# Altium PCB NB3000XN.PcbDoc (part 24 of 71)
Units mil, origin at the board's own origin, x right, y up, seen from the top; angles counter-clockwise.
Board outline 9527.56 x 6929.77 mil, 6 copper layers (Top Layer, GND+SHIELD, MidLayer1, MidLayer2, P2 - 3V3+5V0, Bottom Layer), stack 62.375 mil thick; 832 components, 1027 nets, 4655 pads, 4981 vias.
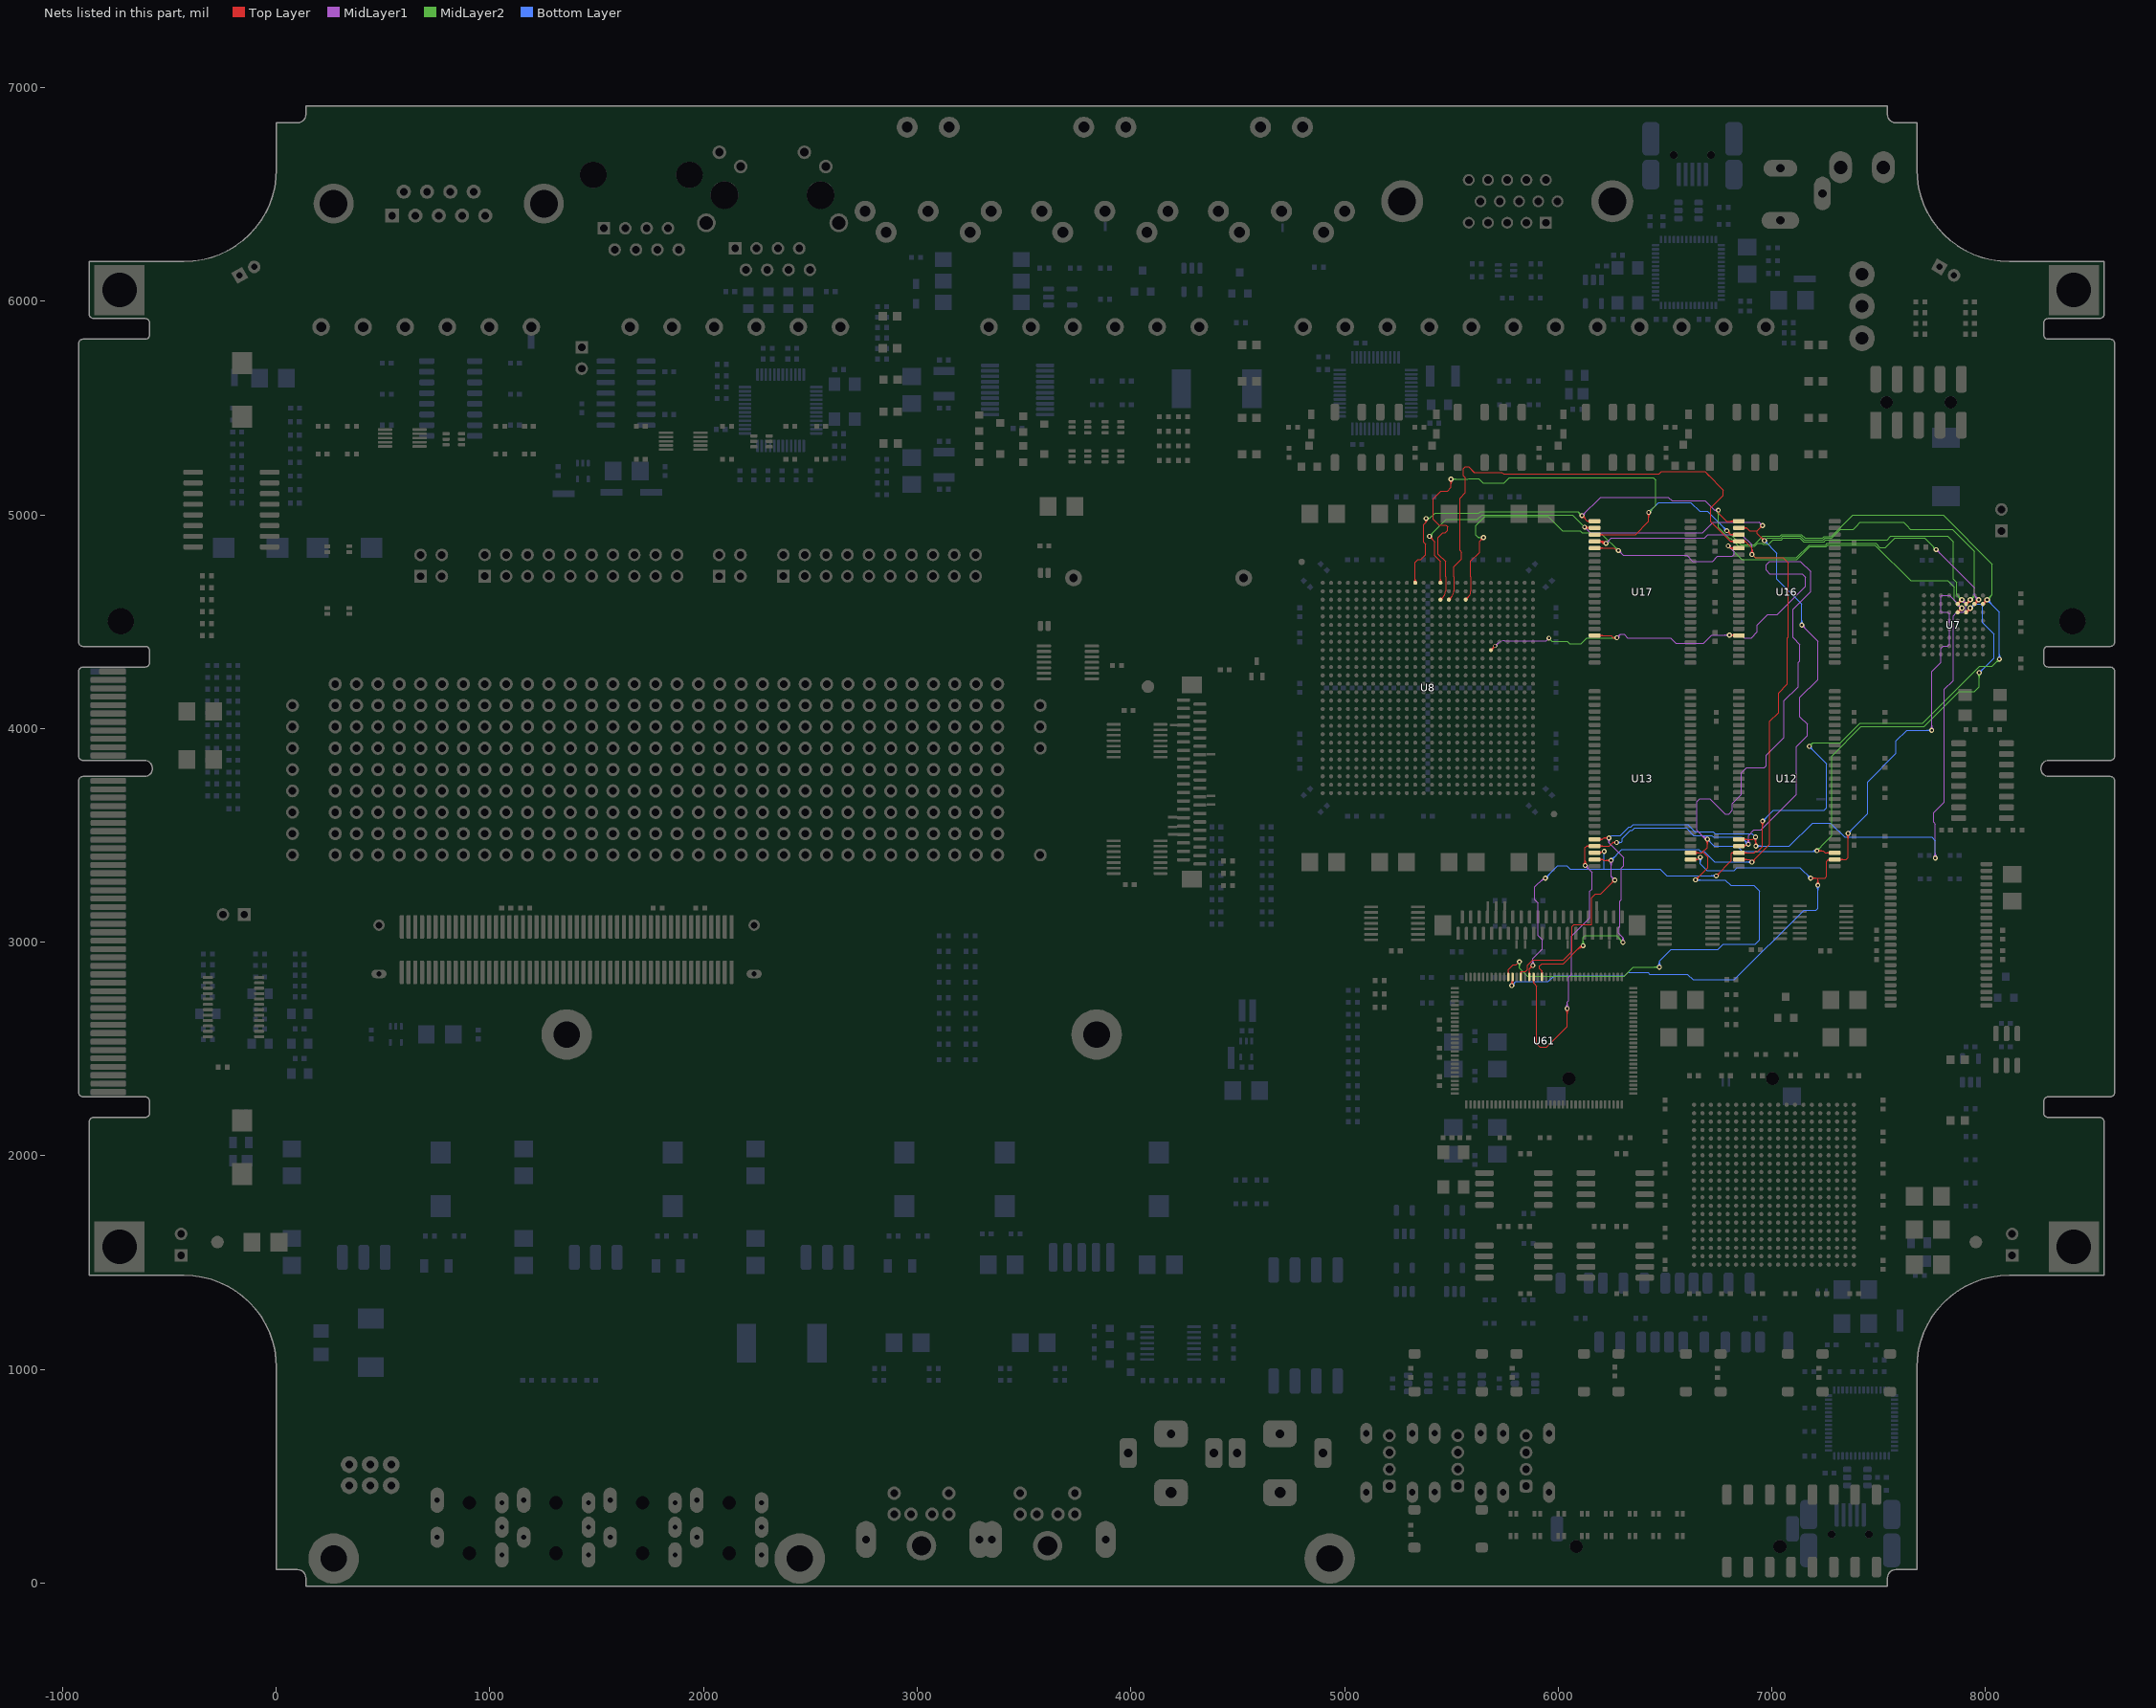
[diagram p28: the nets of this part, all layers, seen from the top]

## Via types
v1: diameter 23, hole 11.81, Top Layer to Bottom Layer, 3672 vias
v2: diameter 26, hole 11.81, Top Layer to Bottom Layer, 461 vias
v3: diameter 19, hole 11.81, Top Layer to Bottom Layer, tented both sides, 396 vias
v4: diameter 23.62, hole 11.81, Top Layer to Bottom Layer, 288 vias
v5: diameter 20, hole 11.81, Top Layer to Bottom Layer, 91 vias
v6: diameter 23, hole 11.81, Top Layer to Bottom Layer, tented both sides, 50 vias
v7: diameter 31, hole 11.81, Top Layer to Bottom Layer, 15 vias
v8: diameter 27.56, hole 11.81, Top Layer to Bottom Layer, tented both sides, 4 vias
v9: diameter 29, hole 11.81, Top Layer to Bottom Layer, 3 vias
v10: diameter 21, hole 11.81, Top Layer to Bottom Layer, 1 vias

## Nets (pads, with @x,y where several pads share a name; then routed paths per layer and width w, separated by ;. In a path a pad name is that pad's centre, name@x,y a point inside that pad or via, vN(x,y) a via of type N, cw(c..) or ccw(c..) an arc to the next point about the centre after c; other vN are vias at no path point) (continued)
DB_MEM.BUS_A2: U7.D2 U8.A12 U12.23 U13.23 U16.1 U17.1 U61.84 | length 9169.9
  Top Layer w4: U8.A12@5325.64,4687.43 ccw(c5312.84,4700.23) 5330.94,4700.23 ccw(c5349.05,4700.23) U8.A12@5336.25,4687.43 ; U8.A12@5325.75,4687.32 ccw(c5313.22,4699.85) 5330.94,4699.85 ccw(c5348.67,4699.85) U8.A12@5336.14,4687.32 ; U8.A12@5330.94,4682.13 5330.94,4710 5330.94,4720 5330.94,4724.74 5330.95,4728.71 5330.95,4778.21 5343.74,4791 5357.13,4791 5379.5,4813.37 5379.5,4863.42 5371.19,4871.73 5371.19,4955.04 5381.86,4965.71 ; v1@5376.62,4975.45 cw(c5370.18,4965.71) 5381.86,4965.71 ; v1(5381.86,4983.37) 5381.86,4965.71 ; v1@5387.1,4975.45 ccw(c5393.53,4965.71) 5381.86,4965.71 ; U61.84@5921.5,2853.36 ccw(c5914.67,2860.19) 5924.33,2860.19 ccw(c5933.99,2860.19) U61.84@5927.16,2853.36 ; U61.84@5924.33,2837.34 5924.33,2864.53 5913.36,2875.5 5913.36,2889.88 5916.78,2893.3 5923.52,2900.04 6024.52,2900.04 6107.86,2983.37 v1(6116.86,2983.37) ; 6085.28,2960.79 cw(c6116.86,2929.21) v1@6116.86,2973.87 ; 6092.1,2967.62 cw(c6116.86,2942.87) v1@6116.86,2977.87 ; 6098.93,2974.45 cw(c6116.86,2956.53) v1@6116.86,2981.87 ; v1@6111.52,4987.21 cw(c6111.52,4964.27) 6127.74,4980.49 cw(c6143.96,4996.71) v1@6121.02,4996.71 ; v1@6111.52,4991.21 cw(c6111.52,4977.93) 6120.91,4987.32 cw(c6130.3,4996.71) v1@6117.02,4996.71 ; v1(6111.52,4996.71) 6137.53,4970.71 ; U17.1@6146.51,4966.07 ccw(c6137.53,4959.68) 6137.53,4970.71 ; U17.1@6146.51,4975.34 cw(c6137.53,4981.73) 6137.53,4970.71 ; U13.23@6170.59,3481.54 6206.35,3481.53 ; U17.1@6170.59,4970.71 6137.53,4970.71 ; U13.23@6194.04,3476.13 cw(c6206.35,3464.83) 6206.35,3481.53 ; U13.23@6194.04,3486.94 ccw(c6206.35,3498.23) 6206.35,3481.53 ; v1@6231.14,3481.32 ccw(c6214.92,3465.11) 6214.92,3488.04 ccw(c6214.92,3510.98) v1@6231.14,3494.76 ; v1@6233.97,3484.15 ccw(c6224.58,3474.76) 6224.58,3488.04 ccw(c6224.58,3501.32) v1@6233.97,3491.93 ; v1(6237.86,3488.04) 6212.86,3488.04 6206.35,3481.53 ; v1(6749.52,5022.37) 6749.52,5008.37 6787.19,4970.71 U16.1@6845.59,4970.71 ; U16.1@6822.37,4965.05 ccw(c6808.72,4951.4) 6808.72,4970.71 ccw(c6808.72,4990.02) U16.1@6822.37,4976.37 ; U12.23@6845.59,3481.54 6912.35,3481.53 v1(6923.52,3492.71) 6923.52,3472 ; U12.23@6868.81,3475.88 cw(c6882.46,3462.22) 6882.46,3481.53 cw(c6882.46,3500.85) U12.23@6868.81,3487.19 ; v1@6917.33,3485.51 cw(c6905.71,3472) 6923.52,3472 ; v1@6919.53,3457.41 ccw(c6909.31,3470) 6925.52,3470 ccw(c6941.74,3470) v1@6931.51,3457.41 ; v1@6919.94,3488.54 cw(c6913.21,3480.72) 6923.52,3480.72 cw(c6933.84,3480.72) v1@6927.11,3488.54 ; v1@6922.06,3454.31 ccw(c6916.14,3461.6) 6925.52,3461.6 ccw(c6934.91,3461.6) v1@6928.99,3454.31 ; v1(6925.52,3450.04) 6925.52,3470 6923.52,3472 ; v1@6929.72,3485.51 ccw(c6941.34,3472) 6923.52,3472
  Top Layer w8: U7.D2@7869.69,4583.43 v2(7889.37,4603.11) ; U7.D2@7869.69,4589.43 ccw(c7869.69,4603.91) 7879.93,4593.67 ccw(c7890.17,4583.43) U7.D2@7875.69,4583.43 ; v2@7880.37,4603.11 cw(c7858.64,4603.11) 7874.01,4587.75 cw(c7889.37,4572.38) v2@7889.37,4594.11
  MidLayer1 w4: v1(6111.52,4996.71) 6198.19,5083.37 6515.19,5083.37 6531.86,5066.71 6687.21,5066.71 6731.54,5022.37 ; v1@6111.52,5002.21 ccw(c6111.52,5015.49) 6120.91,5006.1 ccw(c6130.3,4996.71) v1@6117.02,4996.71 ; v1@6111.52,5006.21 ccw(c6111.52,5029.14) 6127.74,5012.93 ccw(c6143.96,4996.71) v1@6121.02,4996.71 ; v1@6231.14,3481.32 cw(c6214.92,3465.11) 6237.86,3465.11 cw(c6260.79,3465.11) v1@6244.57,3481.32 ; v1@6233.97,3484.15 cw(c6224.58,3474.76) 6237.86,3474.76 cw(c6251.14,3474.76) v1@6241.75,3484.15 ; v1(6237.86,3488.04) 6237.86,3464.69 6307.52,3395.02 6307.52,3358.73 6295.52,3346.73 6295.52,3198.04 6289.19,3191.71 6289.19,3074.04 6281.86,3066.71 6281.86,3041.71 6303.52,3020.04 ; v1@6297.25,3006.18 ccw(c6285.07,3020.04) 6303.52,3020.04 ; v1@6299.89,3003.17 ccw(c6292.84,3011.2) 6303.52,3011.2 ccw(c6314.21,3011.2) v1@6307.16,3003.17 ; v1(6303.52,2999.04) 6303.52,3020.04 ; v1@6309.8,3006.18 cw(c6321.98,3020.04) 6303.52,3020.04 ; v1@6741.68,5017.02 ccw(c6731.54,5010.11) 6731.54,5022.37 ; v1@6741.68,5027.73 cw(c6731.54,5034.64) 6731.54,5022.37 ; v1(6749.52,5022.37) 6731.54,5022.37 ; v1@7758.47,3400.43 ccw(c7742.26,3416.64) 7765.19,3416.64 ccw(c7788.13,3416.64) v1@7771.91,3400.43 ; v1@7761.3,3397.6 ccw(c7751.91,3406.99) 7765.19,3406.99 ccw(c7778.47,3406.99) v1@7769.08,3397.6 ; v1(7765.19,3393.71) 7765.19,3553.69 7756.86,3562.02 7756.86,3606.02 7807.19,3656.35 7807.19,4184.02 7848.52,4225.36 7848.52,4528.04 7865.19,4544.71 7897.52,4544.71 7908.52,4555.71 7908.52,4583.96 v2(7889.37,4603.11) ; v2@7889.37,4592.11 cw(c7889.37,4565.55) 7908.15,4584.33 cw(c7926.93,4603.11) v2@7900.37,4603.11 ; v2@7889.37,4596.11 cw(c7889.37,4579.21) 7901.32,4591.16 cw(c7913.27,4603.11) v2@7896.37,4603.11
  MidLayer2 w4: v1(5381.86,4983.37) 5398.52,4983.37 ; v1@5390.03,4978.53 cw(c5398.52,4973.51) 5398.52,4983.37 ; v1@5390.03,4988.22 ccw(c5398.52,4993.24) 5398.52,4983.37 ; v1@6102.02,4996.71 ccw(c6079.09,4996.71) 6095.31,5012.93 ccw(c6111.52,5029.14) v1@6111.52,5006.21 ; v1@6106.02,4996.71 ccw(c6092.75,4996.71) 6102.14,5006.1 ccw(c6111.52,5015.49) v1@6111.52,5002.21 ; v1@6110.14,2990.09 ccw(c6093.92,3006.31) 6116.86,3006.31 ccw(c6139.79,3006.31) v1@6123.57,2990.09 ; v1(6111.52,4996.71) 6092.03,5016.2 5636.1,5016.2 5628.27,5008.37 5423.52,5008.37 5398.52,4983.37 ; v1@6112.97,2987.26 ccw(c6103.58,2996.65) 6116.86,2996.65 ccw(c6130.14,2996.65) v1@6120.75,2987.26 ; v1(6116.86,2983.37) 6116.86,3021.86 6125,3030 6272.56,3030 v1(6303.52,2999.04) ; v1@6294.02,2999.04 ccw(c6271.09,2999.04) 6287.31,3015.26 ccw(c6303.52,3031.48) v1@6303.52,3008.54 ; v1@6298.02,2999.04 ccw(c6284.75,2999.04) 6294.14,3008.43 ccw(c6303.52,3017.82) v1@6303.52,3004.54 ; v1@6742.81,5015.66 cw(c6726.59,4999.44) 6749.52,4999.44 cw(c6772.46,4999.44) v1@6756.24,5015.66 ; v1@6745.64,5018.49 cw(c6736.25,5009.1) 6749.52,5009.1 cw(c6762.8,5009.1) v1@6753.41,5018.49 ; v1(6749.52,5022.37) 6749.52,4940.71 6801.36,4888.87 6809.4,4888.87 6845.07,4853.21 6920.73,4853.21 6934.23,4866.71 6953.54,4866.71 6957.75,4862.5 6985,4862.5 7006.38,4883.88 7044.62,4883.88 7053.28,4892.54 7130.67,4892.54 7148,4875.21 7244.15,4875.21 7252.15,4883.21 7540.02,4883.21 7540.19,4883.37 7556.86,4900.04 7823.52,4900.04 7848.52,4875.04 7848.52,4700.04 7865.19,4683.37 7865.19,4627.29 v2(7889.37,4603.11) ; v2@7878.37,4603.11 ccw(c7851.82,4603.11) 7870.59,4621.89 ccw(c7889.37,4640.67) v2@7889.37,4614.11 ; v2@7882.37,4603.11 ccw(c7865.47,4603.11) 7877.42,4615.06 ccw(c7889.37,4627.01) v2@7889.37,4610.11
  Bottom Layer w4: v1(6237.86,3488.04) 6249.86,3500.04 6291.19,3500.04 6330.86,3539.71 6340,3539.71 6350.67,3550.37 6606.52,3550.37 6640.19,3516.71 6725.52,3516.71 6733.86,3508.37 6907.86,3508.37 v1(6923.52,3492.71) ; v1(6925.52,3450.04) 7081.86,3450.04 7190.19,3558.37 7273.52,3558.37 7340.19,3491.71 7748.52,3491.71 7765.19,3475.04 v1(7765.19,3393.71) ; v1@6929.41,3446.15 cw(c6938.8,3436.76) 6938.8,3450.04 cw(c6938.8,3463.32) v1@6929.41,3453.93 ; v1@6932.24,3443.32 cw(c6948.46,3427.11) 6948.46,3450.04 cw(c6948.46,3472.98) v1@6932.24,3456.76 ; v1@7758.47,3400.43 ccw(c7742.26,3416.64) 7765.19,3416.64 ccw(c7788.13,3416.64) v1@7771.91,3400.43 ; v1@7761.3,3397.6 ccw(c7751.91,3406.99) 7765.19,3406.99 ccw(c7778.47,3406.99) v1@7769.08,3397.6
DB_MEM.BUS_A3: U7.C2 U8.A15 U12.24 U13.24 U16.2 U17.2 U61.86 | length 8910.3
  Top Layer w4: v1@5397.19,4890.54 cw(c5397.19,4867.61) 5413.41,4883.82 cw(c5429.63,4900.04) v1@5406.69,4900.04 ; v1@5397.19,4894.54 cw(c5397.19,4881.26) 5406.58,4890.65 cw(c5415.97,4900.04) v1@5402.69,4900.04 ; v1(5397.19,4900.04) 5422.5,4874.73 5422.5,4809.73 5449.06,4783.17 5449.06,4720 5449.06,4710 U8.A15@5449.06,4682.13 ; U8.A15@5443.75,4687.43 ccw(c5430.95,4700.23) 5449.06,4700.23 ccw(c5467.16,4700.23) U8.A15@5454.36,4687.43 ; U8.A15@5443.86,4687.32 ccw(c5431.33,4699.85) 5449.06,4699.85 ccw(c5466.78,4699.85) U8.A15@5454.25,4687.32 ; U61.86@5882.13,2821.32 cw(c5875.3,2814.49) 5884.96,2814.49 cw(c5894.62,2814.49) U61.86@5887.79,2821.32 ; U61.86@5884.96,2837.34 5884.96,2808.37 5898.52,2794.81 5898.52,2525.04 5915.19,2508.37 5945.54,2508.37 6041.86,2604.69 v1(6041.86,2689.71) ; v1@6035.14,2682.99 cw(c6018.92,2666.77) 6041.86,2666.77 cw(c6064.79,2666.77) v1@6048.57,2682.99 ; v1@6037.97,2685.82 cw(c6028.58,2676.43) 6041.86,2676.43 cw(c6055.14,2676.43) v1@6045.75,2685.82 ; v1@6119.47,3366.09 ccw(c6103.26,3382.31) 6126.19,3382.31 ccw(c6149.13,3382.31) v1@6132.91,3366.09 ; v1@6122.3,3363.26 ccw(c6112.91,3372.65) 6126.19,3372.65 ccw(c6139.47,3372.65) v1@6130.08,3363.26 ; v1(6123.52,4943.04) 6127.35,4939.21 U17.2@6170.59,4939.21 ; v1@6124.58,4944.1 ccw(c6136.38,4955.9) 6136.38,4939.21 ; v1(6126.19,3359.37) 6126.19,3443.04 6133.19,3450.04 6240.19,3450.04 6256.86,3466.71 ; v1@6127.41,4946.93 ccw(c6146.04,4965.56) U17.2@6146.04,4939.21 ; v1@6130.24,4936.32 cw(c6137.22,4929.34) 6137.22,4939.21 ; v1@6130.24,4949.76 ccw(c6155.7,4975.21) U17.2@6155.7,4939.21 ; U13.24@6147.37,3444.38 ccw(c6133.72,3430.73) 6133.72,3450.04 ccw(c6133.72,3469.35) U13.24@6147.37,3455.7 ; U17.2@6147.37,4933.56 ccw(c6133.72,4919.9) 6133.72,4939.21 ccw(c6133.72,4958.53) U17.2@6147.37,4944.87 ; U13.24@6193.81,3444.38 cw(c6207.46,3430.73) 6207.46,3450.04 cw(c6207.46,3469.35) U13.24@6193.81,3455.7 ; v1@6265.35,3461.87 ccw(c6256.86,3456.84) 6256.86,3466.71 ; v1@6265.35,3471.55 cw(c6256.86,3476.58) 6256.86,3466.71 ; v1(6273.52,3466.71) 6256.86,3466.71 ; U12.24@6845.59,3450.04 6874.19,3450.04 ; U16.2@6845.59,4939.21 6881.15,4939.21 ; U12.24@6863.15,3450.04 ccw(c6868.51,3458.36) 6875.51,3451.36 ; U12.24@6865.32,3453.4 ccw(c6871.26,3462.63) 6879.02,3454.87 ; U12.24@6867.48,3456.77 ccw(c6874.01,3466.89) v1@6882.52,3458.37 ; U16.2@6869.09,4933.85 cw(c6881.15,4922.96) 6881.15,4939.21 ; U16.2@6869.09,4944.57 ccw(c6881.15,4955.46) 6881.15,4939.21 ; U12.24@6870.75,3447.55 cw(c6874.19,3446.42) 6874.19,3450.04 ; U12.24@6870.75,3452.53 ccw(c6874.19,3453.65) 6874.19,3450.04 ; 6874.65,3450.5 cw(c6883.5,3441.64) v1@6888.15,3453.27 ; 6878.94,3454.79 cw(c6885.95,3447.77) v1@6889.63,3456.98 ; v1(6890.19,3458.37) v1@6882.52,3458.37 ; v1@6947.36,4950.04 cw(c6924.42,4950.04) 6940.64,4933.82 cw(c6956.86,4917.61) v1@6956.86,4940.54 ; v1@6951.36,4950.04 cw(c6938.08,4950.04) 6947.47,4940.65 cw(c6956.86,4931.26) v1@6956.86,4944.54 ; v1@6955.5,4880 ccw(c6932.56,4880) 6948.78,4896.22 ccw(c6965,4912.43) v1@6965,4889.5 ; v1(6956.86,4950.04) 6931.86,4925.04 ; v1@6959.5,4880 ccw(c6946.22,4880) 6955.61,4889.39 ccw(c6965,4898.78) v1@6965,4885.5 ; v1(6965,4880) 6931.86,4913.14 6931.86,4925.04 ; 6874.19,3450.04 v1@6882.52,3458.37 ; 6881.15,4939.21 6895.32,4925.04 6931.86,4925.04
  Top Layer w8: U7.C2@7909.06,4583.43 v2(7928.74,4603.11) ; U7.C2@7909.06,4589.43 ccw(c7909.06,4603.91) 7919.3,4593.67 ccw(c7929.54,4583.43) U7.C2@7915.06,4583.43 ; v2@7919.74,4603.11 cw(c7898.01,4603.11) 7913.38,4587.75 cw(c7928.74,4572.38) v2@7928.74,4594.11
  MidLayer1 w4: v1@6035.14,2696.43 ccw(c6018.92,2712.64) 6041.86,2712.64 ccw(c6064.79,2712.64) v1@6048.57,2696.43 ; v1@6037.97,2693.6 ccw(c6028.58,2702.99) 6041.86,2702.99 ccw(c6055.14,2702.99) v1@6045.75,2693.6 ; v1(6041.86,2689.71) 6041.86,2720.75 6048.52,2727.41 6048.52,2835.71 6062.86,2850.04 6062.86,3028.35 6148.52,3114.02 6148.52,3238.67 6158.19,3248.34 6158.19,3327.37 v1(6126.19,3359.37) ; v1@6123.52,4933.54 cw(c6123.52,4910.61) 6139.74,4926.82 cw(c6155.96,4943.04) v1@6133.02,4943.04 ; v1@6123.52,4937.54 cw(c6123.52,4924.26) 6132.91,4933.65 cw(c6142.3,4943.04) v1@6129.02,4943.04 ; v1(6123.52,4943.04) 6149.86,4916.71 6675.88,4916.71 6725.88,4966.71 6940.19,4966.71 v1(6956.86,4950.04) ; v1@6126.19,3349.87 cw(c6126.19,3326.94) 6142.41,3343.16 cw(c6158.63,3359.37) v1@6135.69,3359.37 ; v1@6126.19,3353.87 cw(c6126.19,3340.6) 6135.58,3349.99 cw(c6144.97,3359.37) v1@6131.69,3359.37 ; v1@6883.47,3465.09 ccw(c6867.26,3481.31) 6890.19,3481.31 ccw(c6913.13,3481.31) v1@6896.91,3465.09 ; v1@6886.3,3462.26 ccw(c6876.91,3471.65) 6890.19,3471.65 ccw(c6903.47,3471.65) v1@6894.08,3462.26 ; v1(6890.19,3458.37) 6890.19,3500.04 6915.19,3525.04 6948.52,3525.04 7115.19,3691.71 7115.19,3916.35 7165.52,3966.69 7165.52,4020.79 7131.86,4054.46 7131.86,4146.45 7215.19,4229.79 7215.19,4409.37 v1(7140.19,4484.37) ; v1@6947.36,4950.04 ccw(c6924.42,4950.04) 6940.64,4966.26 ccw(c6956.86,4982.48) v1@6956.86,4959.54 ; v1@6951.36,4950.04 ccw(c6938.08,4950.04) 6947.47,4959.43 ccw(c6956.86,4968.82) v1@6956.86,4955.54 ; v1@7140.19,4474.87 cw(c7140.19,4451.94) 7156.41,4468.16 cw(c7172.63,4484.37) v1@7149.69,4484.37 ; v1@7140.19,4478.87 cw(c7140.19,4465.6) 7149.58,4474.99 cw(c7158.97,4484.37) v1@7145.69,4484.37
  MidLayer2 w4: v1(5397.19,4900.04) 5476.52,4979.37 5621.9,4979.37 5642.73,5000.2 6039.8,5000.2 ; v1@5397.19,4905.54 ccw(c5397.19,4918.82) 5406.58,4909.43 ccw(c5415.97,4900.04) v1@5402.69,4900.04 ; v1@5397.19,4909.54 ccw(c5397.19,4932.48) 5413.41,4916.26 ccw(c5429.63,4900.04) v1@5406.69,4900.04 ; 6040,5000 6039.8,5000.2 ; v1(6123.52,4943.04) 6066.36,5000.2 6039.8,5000.2 ; v1(6965,4880) 6978.04,4893.04 7042.47,4893.04 7049.97,4900.54 7133.98,4900.54 7151.31,4883.21 7240.84,4883.21 7248.84,4891.21 7281.26,4891.21 7322.09,4932.04 7380.52,4932.04 7398.52,4950.04 ; 7396.8,4948.32 7413.48,4965 7616.9,4965 7631.86,4950.04 7648.52,4933.37 7845.54,4933.37 7948.52,4830.39 7948.52,4622.89 v2(7928.74,4603.11) ; v2@7928.74,4610.11 ccw(c7928.74,4627.01) 7940.69,4615.06 ccw(c7952.64,4603.11) v2@7935.74,4603.11 ; v2@7928.74,4614.11 ccw(c7928.74,4640.67) 7947.52,4621.89 ccw(c7966.3,4603.11) v2@7939.74,4603.11
  Bottom Layer w4: v1(6273.52,3466.71) 6295.52,3466.71 ; v1@6277.53,3462.94 cw(c6286.26,3454.71) 6286.26,3466.71 cw(c6286.26,3478.7) v1@6277.53,3470.48 ; v1@6280.44,3460.19 cw(c6295.52,3445.99) 6295.52,3466.71 ; v1@6280.44,3473.22 ccw(c6295.52,3487.43) 6295.52,3466.71 ; v1@6880.69,3458.37 ccw(c6857.76,3458.37) 6873.97,3474.59 ccw(c6890.19,3490.81) v1@6890.19,3467.87 ; v1@6884.69,3458.37 ccw(c6871.41,3458.37) 6880.8,3467.76 ccw(c6890.19,3477.15) v1@6890.19,3463.87 ; v1(6890.19,3458.37) 6856.86,3491.71 6727.9,3491.71 6719.56,3500.04 6634.23,3500.04 6599.9,3534.37 6357.29,3534.37 6346.63,3523.71 6337.48,3523.71 6300.21,3486.43 6300.21,3471.39 6295.52,3466.71 ; v1@6965,4870.5 cw(c6965,4847.56) 6981.22,4863.78 cw(c6997.43,4880) v1@6974.5,4880 ; v1(6965,4880) 7023.52,4821.48 7023.52,4700.37 7140.19,4583.71 v1(7140.19,4484.37) ; v1@7133.47,4491.09 ccw(c7117.26,4507.31) 7140.19,4507.31 ccw(c7163.13,4507.31) v1@7146.91,4491.09 ; v1@7136.3,4488.26 ccw(c7126.91,4497.65) 7140.19,4497.65 ccw(c7153.47,4497.65) v1@7144.08,4488.26 ; 6974.39,4870.61 cw(c6983.78,4880) 6970.5,4880 ccw(c6983.78,4880) 6974.39,4870.61 ; 6974.39,4870.61 ccw(c6965,4861.22) 6965,4874.5 cw(c6965,4861.22) 6974.39,4870.61
DB_MEM.BUS_A4: U7.A2 U8.C15 U12.25 U13.25 U16.3 U17.3 U61.87 | length 9796.5
  Top Layer w4: U8.C15@5449.06,4610.73 ccw(c5449.06,4628.45) 5461.59,4615.92 ; U8.C15@5456.4,4603.39 cw(c5474.12,4603.39) 5461.59,4615.92 ; 5472.92,4773.31 5472.92,4765 ; v1@5491.81,5160.99 cw(c5475.59,5144.77) 5498.52,5144.77 cw(c5521.46,5144.77) v1@5505.24,5160.99 ; v1@5494.64,5163.82 cw(c5485.25,5154.43) 5498.52,5154.43 cw(c5511.8,5154.43) v1@5502.41,5163.82 ; v1@5498.52,5158.37 v1(5498.52,5167.71) 5498.52,5128.52 5481.75,5111.75 5451.9,5111.75 5415.19,5075.04 5415.19,4978.71 5441.52,4952.37 5441.65,4952.5 5474.4,4952.5 5474.52,4952.37 5481.86,4945.04 5482.5,4944.4 5482.5,4927.75 5470.75,4916 5461.15,4916 5438.86,4893.71 5438.86,4816 5472.92,4781.94 5472.92,4765 ; U61.87@5862.45,2853.36 ccw(c5855.82,2859.98) 5865.19,2859.98 ; 5864.86,2874.71 cw(c5881.36,2858.2) v1@5881.71,2881.54 ; U61.87@5865.19,2850.53 5865.19,2875.04 5881.19,2891.04 v1(5881.86,2891.04) ; 5865.19,2860.39 ccw(c5875.14,2860.39) U61.87@5868.1,2853.36 ; 5866.11,2875.96 ccw(c5851.03,2891.04) v1@5872.36,2891.04 ; 5871.54,2881.39 cw(c5881.56,2871.38) v1@5881.77,2885.54 ; 5872.94,2882.79 ccw(c5864.69,2891.04) v1@5876.36,2891.04 ; U13.25@6170.59,3418.54 6200,3418.54 ; U17.3@6170.59,4907.72 6361.55,4907.72 6423.86,4970.02 v1(6423.86,5012.04) ; U13.25@6188.15,3418.54 ccw(c6194.06,3425.34) 6200.43,3418.97 ; U13.25@6190.77,3421.56 ccw(c6196.88,3428.59) 6203.46,3422.01 ; U13.25@6193.4,3424.58 ccw(c6199.7,3431.84) v1@6206.5,3425.04 ; U17.3@6193.81,4902.06 cw(c6207.46,4888.4) 6207.46,4907.72 cw(c6207.46,4927.03) U17.3@6193.81,4913.37 ; U13.25@6195.57,3415.55 cw(c6200,3413.77) 6200,3418.54 ; U13.25@6195.57,3421.53 ccw(c6200,3423.32) 6200,3418.54 ; v1(6215.19,3425.04) v1@6206.5,3425.04 ; v1@6417.14,5005.32 cw(c6400.92,4989.11) 6423.86,4989.11 cw(c6446.79,4989.11) v1@6430.57,5005.32 ; v1@6419.97,5008.15 cw(c6410.58,4998.76) 6423.86,4998.76 cw(c6437.14,4998.76) v1@6427.75,5008.15 ; v1(6740.19,3310.71) 6811.52,3382.04 6811.52,3416.88 6813.19,3418.54 ; v1@6740.19,3316.21 ccw(c6740.19,3329.49) 6749.58,3320.1 ccw(c6758.97,3310.71) v1@6745.69,3310.71 ; v1@6740.19,3320.21 ccw(c6740.19,3343.14) 6756.41,3326.93 ccw(c6772.63,3310.71) v1@6749.69,3310.71 ; v1@6789.52,4916.87 cw(c6789.52,4893.94) 6805.74,4910.16 cw(c6821.96,4926.37) v1@6799.02,4926.37 ; v1@6789.52,4920.87 cw(c6789.52,4907.6) 6798.91,4916.99 cw(c6808.3,4926.37) v1@6795.02,4926.37 ; v1(6789.52,4926.37) 6808.18,4907.72 U16.3@6845.59,4907.72 ; U12.25@6821.35,3422.94 cw(c6813.19,3428.31) 6813.19,3418.54 ; U12.25@6821.35,3414.15 ccw(c6813.19,3408.78) 6813.19,3418.54 ; U16.3@6822.37,4902.06 ccw(c6808.72,4888.4) 6808.72,4907.72 ccw(c6808.72,4927.03) U16.3@6822.37,4913.37 ; U12.25@6868.81,3412.89 cw(c6882.46,3399.23) 6882.46,3418.54 cw(c6882.46,3437.86) U12.25@6868.81,3424.2 ; v1@6950.14,3559.99 cw(c6933.92,3543.77) 6956.86,3543.77 cw(c6979.79,3543.77) v1@6963.57,3559.99 ; v1@6952.97,3562.82 cw(c6943.58,3553.43) 6956.86,3553.43 cw(c6970.14,3553.43) v1@6960.75,3562.82 ; v1(6956.86,3566.71) 6956.86,3448.37 6933.52,3425.04 6923.52,3425.04 6917.03,3418.54 U12.25@6845.59,3418.54 6813.19,3418.54 ; 5461.59,4615.92 ccw(c5434.24,4643.27) 5472.92,4643.27 5472.92,4710 5472.92,4720 5472.92,4765 ; 6200,3418.54 v1@6206.5,3425.04
  Top Layer w8: U7.A2@7987.8,4583.43 v2(8007.48,4603.11) ; U7.A2@7987.8,4589.43 ccw(c7987.8,4603.91) 7998.04,4593.67 ccw(c8008.28,4583.43) U7.A2@7993.8,4583.43 ; v2@7998.48,4603.11 cw(c7976.75,4603.11) 7992.12,4587.75 cw(c8007.48,4572.38) v2@8007.48,4594.11
  MidLayer1 w4: v1@5875.14,2897.76 ccw(c5858.92,2913.98) 5881.86,2913.98 ccw(c5904.79,2913.98) v1@5888.57,2897.76 ; v1@5877.97,2894.93 ccw(c5868.58,2904.32) 5881.86,2904.32 ccw(c5895.14,2904.32) v1@5885.75,2894.93 ; v1(5881.86,2891.04) 5881.86,2923.37 5926.19,2967.71 5926.19,3011.06 5906.19,3031.06 5906.19,3182.67 5890.86,3198 5890.86,3259.04 5931.86,3300.04 v1(5940.19,3300.04) ; 5909.75,3277.93 cw(c5940.19,3247.49) v1@5940.19,3290.54 ; 5916.58,3284.76 cw(c5940.19,3261.14) v1@5940.19,3294.54 ; 5923.4,3291.59 cw(c5940.19,3274.8) v1@5940.19,3298.54
  MidLayer2 w4: v1(5498.52,5167.71) 5577.71,5167.71 5580,5170 5628.56,5170 5648.52,5150.04 5746.86,5150.04 5771.86,5175.04 6445.54,5175.04 6457.19,5163.39 6457.19,5045.37 v1(6423.86,5012.04) ; v1@5502.41,5163.82 cw(c5511.8,5154.43) 5511.8,5167.71 cw(c5511.8,5180.99) v1@5502.41,5171.6 ; v1@5505.24,5160.99 cw(c5521.46,5144.77) 5521.46,5167.71 cw(c5521.46,5190.64) v1@5505.24,5174.43 ; v1@6423.86,5017.54 ccw(c6423.86,5030.82) 6433.25,5021.43 ccw(c6442.64,5012.04) v1@6429.36,5012.04 ; v1@6423.86,5021.54 ccw(c6423.86,5044.48) 6440.07,5028.26 ccw(c6456.29,5012.04) v1@6433.36,5012.04 ; v1@6789.52,4916.87 cw(c6789.52,4893.94) 6805.74,4910.16 cw(c6821.96,4926.37) v1@6799.02,4926.37 ; v1@6789.52,4920.87 cw(c6789.52,4907.6) 6798.91,4916.99 cw(c6808.3,4926.37) v1@6795.02,4926.37 ; v1(6789.52,4926.37) 6854.69,4861.21 6917.42,4861.21 6957.25,4901.04 7039.15,4901.04 ; v1(7174.86,3916.71) 7191.52,3933.37 7295,3933.37 7306.86,3933.37 7320.54,3933.37 7412.21,4025.04 7460,4025.04 7706.86,4025.04 7973.52,4291.71 8031.86,4291.71 v1(8065.19,4325.04) ; v1@7174.86,3922.21 ccw(c7174.86,3935.49) 7184.25,3926.1 ccw(c7193.64,3916.71) v1@7180.36,3916.71 ; v1@7174.86,3926.21 ccw(c7174.86,3949.14) 7191.07,3932.93 ccw(c7207.29,3916.71) v1@7184.36,3916.71 ; v2(8007.48,4603.11) 8031.86,4627.49 8031.86,4769.69 7801.5,5000.04 7378.78,5000.04 7277.94,4899.21 7245.52,4899.21 7237.52,4891.21 7154.63,4891.21 7137.29,4908.54 7046.65,4908.54 7041.11,4903 ; v2@8007.48,4610.11 ccw(c8007.48,4627.01) 8019.43,4615.06 ccw(c8031.38,4603.11) v2@8014.48,4603.11 ; v2@8007.48,4614.11 ccw(c8007.48,4640.67) 8026.26,4621.89 ccw(c8045.03,4603.11) v2@8018.48,4603.11 ; v1@8055.69,4325.04 cw(c8032.76,4325.04) 8048.97,4308.82 cw(c8065.19,4292.61) v1@8065.19,4315.54 ; v1@8059.69,4325.04 cw(c8046.41,4325.04) 8055.8,4315.65 cw(c8065.19,4306.26) v1@8065.19,4319.54 ; 7039.15,4901.04 7041.11,4903 ; 7039.15,4901.04 7041.11,4903
  Bottom Layer w4: v1(5940.19,3300.04) 5998.52,3358.37 6040.19,3358.37 6056.86,3341.71 6215.19,3341.71 ; v1@5940.19,3305.54 ccw(c5940.19,3318.82) 5949.58,3309.43 ccw(c5958.97,3300.04) v1@5945.69,3300.04 ; v1@5940.19,3309.54 ccw(c5940.19,3332.48) 5956.41,3316.26 ccw(c5972.63,3300.04) v1@5949.69,3300.04 ; v1(6215.19,3425.04) 6215.19,3341.71 ; v1(6423.86,5012.04) 6470.19,5058.37 6621.21,5058.37 6662.88,5016.71 6699.19,5016.71 v1(6789.52,4926.37) ; v1@6423.86,5017.54 ccw(c6423.86,5030.82) 6433.25,5021.43 ccw(c6442.64,5012.04) v1@6429.36,5012.04 ; v1@6423.86,5021.54 ccw(c6423.86,5044.48) 6440.07,5028.26 ccw(c6456.29,5012.04) v1@6433.36,5012.04 ; v1@6733.47,3303.99 ccw(c6717.26,3287.77) 6717.26,3310.71 ccw(c6717.26,3333.64) v1@6733.47,3317.43 ; v1@6736.3,3306.82 ccw(c6726.91,3297.43) 6726.91,3310.71 ccw(c6726.91,3323.99) v1@6736.3,3314.6 ; v1(6740.19,3310.71) 6508.61,3310.71 6477.61,3341.71 6215.19,3341.71 ; v1@6780.02,4926.37 ccw(c6757.09,4926.37) 6773.31,4942.59 ccw(c6789.52,4958.81) v1@6789.52,4935.87 ; v1@6784.02,4926.37 ccw(c6770.75,4926.37) 6780.14,4935.76 ccw(c6789.52,4945.15) v1@6789.52,4931.87 ; v1(6956.86,3566.71) 7006.86,3616.71 7245.54,3616.71 7257.19,3628.35 7257.19,3834.37 v1(7174.86,3916.71) ; v1@6956.86,3572.21 ccw(c6956.86,3585.49) 6966.25,3576.1 ccw(c6975.64,3566.71) v1@6962.36,3566.71 ; v1@6956.86,3576.21 ccw(c6956.86,3599.14) 6973.07,3582.93 ccw(c6989.29,3566.71) v1@6966.36,3566.71 ; v1@7174.86,3907.21 cw(c7174.86,3884.27) 7191.07,3900.49 cw(c7207.29,3916.71) v1@7184.36,3916.71 ; v1@7174.86,3911.21 cw(c7174.86,3897.93) 7184.25,3907.32 cw(c7193.64,3916.71) v1@7180.36,3916.71 ; v2@8007.48,4592.11 cw(c8007.48,4565.55) 8026.26,4584.33 cw(c8045.04,4603.11) v2@8018.48,4603.11 ; v2@8007.48,4596.11 cw(c8007.48,4579.21) 8019.43,4591.16 cw(c8031.38,4603.11) v2@8014.48,4603.11 ; v2(8007.48,4603.11) 8065.19,4545.4 v1(8065.19,4325.04) ; v1@8058.47,4331.76 ccw(c8042.26,4347.98) 8065.19,4347.98 ccw(c8088.13,4347.98) v1@8071.91,4331.76 ; v1@8061.3,4328.93 ccw(c8051.91,4338.32) 8065.19,4338.32 ccw(c8078.47,4338.32) v1@8069.08,4328.93
DB_MEM.BUS_A5: U7.B2 U8.C16 U12.26 U13.26 U16.4 U17.4 U61.89 | length 9055.1
  Top Layer w4: U8.C16@5488.43,4610.73 ccw(c5488.43,4628.45) 5500.96,4615.92 ; U8.C16@5495.77,4603.39 cw(c5513.49,4603.39) 5500.96,4615.92 ; 5606.86,5199.37 5581.19,5225.04 ; 5770.63,5191.37 5791,5191.37 ; U61.89@5823.08,2853.36 ccw(c5816.25,2860.19) 5825.91,2860.19 ccw(c5835.56,2860.19) U61.89@5828.73,2853.36 ; U61.89@5825.9,2837.34 5825.91,2861.71 5827.57,2863.37 5848.52,2863.37 5856.86,2871.71 5856.86,2891.71 5881.86,2916.71 6025.19,2916.71 6065.19,2956.71 6065.19,3073.71 6073.52,3082.04 6155.19,3082.04 6156.86,3083.71 6156.86,3208.37 6173.52,3225.04 6199.52,3225.04 v1(6265.19,3290.71) ; U13.26@6170.59,3387.05 6209.53,3387.05 6213.2,3383.37 v1(6247.52,3383.37) ; U17.4@6170.59,4876.22 6214.01,4876.22 v1(6223.52,4866.71) ; U17.4@6177.63,4876.22 cw(c6177.63,4820.81) v1@6216.81,4859.99 ; U17.4@6187.28,4876.22 cw(c6187.28,4830.47) v1@6219.64,4862.82 ; U13.26@6193.81,3381.39 cw(c6207.46,3367.73) 6207.46,3387.05 cw(c6207.46,3406.36) U13.26@6193.81,3392.7 ; U17.4@6193.81,4870.56 cw(c6207.46,4856.91) 6207.46,4876.22 cw(c6207.46,4895.53) U17.4@6193.81,4881.88 ; U17.4@6196.94,4876.22 cw(c6196.94,4840.12) v1@6222.46,4865.65 ; 6206.6,4876.22 cw(c6206.6,4849.78) v1@6225.29,4868.48 ; v1@6240.81,3376.66 ccw(c6224.59,3360.44) 6224.59,3383.37 ccw(c6224.59,3406.31) v1@6240.81,3390.09 ; v1@6243.64,3379.49 ccw(c6234.25,3370.1) 6234.25,3383.37 ccw(c6234.25,3396.65) v1@6243.64,3387.26 ; v1@6255.69,3290.71 cw(c6232.76,3290.71) 6248.97,3274.49 cw(c6265.19,3258.27) v1@6265.19,3281.21 ; v1@6259.69,3290.71 cw(c6246.41,3290.71) 6255.8,3281.32 cw(c6265.19,3271.93) v1@6265.19,3285.21 ; 6697.52,5191.71 6773.52,5115.71 6773.52,5090.37 6715.19,5032.04 6715.19,4967.89 6806.86,4876.22 U16.4@6845.59,4876.22 6876.35,4876.22 ; 6706.29,5182.94 6686.52,5202.71 6526.82,5202.71 6505,5202.71 6483.37,5202.71 6472.04,5191.37 5791,5191.37 ; U16.4@6822.37,4870.56 ccw(c6808.72,4856.91) 6808.72,4876.22 ccw(c6808.72,4895.53) U16.4@6822.37,4881.88 ; U12.26@6845.59,3387.05 6894.86,3387.05 v1(6906.86,3375.04) 6990.19,3458.37 6990.19,4033.37 7031.86,4075.04 7031.86,4166.71 7073.52,4208.37 7073.52,4425.04 7076.86,4428.37 7076.86,4775.04 7051.86,4800.04 6921.86,4800.04 v1(6906.86,4815.04) 6906.86,4845.71 6876.35,4876.22 ; U12.26@6868.81,3381.39 cw(c6882.46,3367.73) 6882.46,3387.05 cw(c6882.46,3406.36) U12.26@6868.81,3392.7 ; U16.4@6870.24,4872.52 cw(c6876.34,4869.34) 6876.34,4876.22 ; U16.4@6870.24,4879.92 ccw(c6876.34,4883.1) 6876.34,4876.22 ; v1@6900.14,4821.76 ccw(c6883.92,4837.98) 6906.86,4837.98 ccw(c6929.79,4837.98) v1@6913.57,4821.76 ; v1@6902.97,4818.93 ccw(c6893.58,4828.32) 6906.86,4828.32 ccw(c6920.14,4828.32) v1@6910.75,4818.93 ; v1@6906.86,3380.54 ccw(c6906.86,3393.82) 6916.25,3384.43 ccw(c6925.64,3375.04) v1@6912.36,3375.04 ; v1@6906.86,3384.54 ccw(c6906.86,3407.48) 6923.07,3391.26 ccw(c6939.29,3375.04) v1@6916.36,3375.04 ; 5500.96,4615.92 ccw(c5473.61,4643.27) 5512.29,4643.27 5512.29,4710 5512.29,4720 5512.29,4724.74 5512.29,4756.71 5548.52,4792.94 5548.52,4825.04 5540.19,4833.37 5540.19,5078.33 5540.52,5078.33 5566.52,5104.33 5566.52,5173.48 5556.86,5183.14 5556.86,5217.37 5564.52,5225.04 5581.19,5225.04 ; 5581.19,5225.04 5607.23,5199 5736.65,5199 5744.27,5191.37 5791,5191.37
  Top Layer w8: U7.B2@7948.43,4583.43 v2(7968.11,4603.11) ; U7.B2@7948.43,4589.43 ccw(c7948.43,4603.91) 7958.67,4593.67 ccw(c7968.91,4583.43) U7.B2@7954.43,4583.43 ; v2@7959.11,4603.11 cw(c7937.38,4603.11) 7952.75,4587.75 cw(c7968.11,4572.38) v2@7968.11,4594.11
  MidLayer1 w4: v1(6223.52,4866.71) 6248.52,4891.71 6684.84,4891.71 6701.51,4908.37 6858.19,4908.37 6906.86,4859.71 v1(6906.86,4815.04) ; v1@6223.52,4872.21 ccw(c6223.52,4885.49) 6232.91,4876.1 ccw(c6242.3,4866.71) v1@6229.02,4866.71 ; v1@6223.52,4876.21 ccw(c6223.52,4899.14) 6239.74,4882.93 ccw(c6255.96,4866.71) v1@6233.02,4866.71 ; v1@6240.81,3376.66 cw(c6224.59,3360.44) 6247.52,3360.44 cw(c6270.46,3360.44) v1@6254.24,3376.66 ; v1@6243.64,3379.49 cw(c6234.25,3370.1) 6247.52,3370.1 cw(c6260.8,3370.1) v1@6251.41,3379.49 ; v1(6247.52,3383.37) 6247.52,3308.37 v1(6265.19,3290.71) ; v1@6255.69,3290.71 ccw(c6232.76,3290.71) 6248.97,3306.93 ccw(c6265.19,3323.14) v1@6265.19,3300.21 ; v1@6259.69,3290.71 ccw(c6246.41,3290.71) 6255.8,3300.1 ccw(c6265.19,3309.49) v1@6265.19,3296.21 ; v1@6900.14,4821.76 ccw(c6883.92,4837.98) 6906.86,4837.98 ccw(c6929.79,4837.98) v1@6913.57,4821.76 ; v1@6902.97,4818.93 ccw(c6893.58,4828.32) 6906.86,4828.32 ccw(c6920.14,4828.32) v1@6910.75,4818.93 ; v1@7769.19,4828.21 cw(c7769.19,4805.27) 7785.41,4821.49 cw(c7801.63,4837.71) v1@7778.69,4837.71 ; v1@7769.19,4832.21 cw(c7769.19,4818.93) 7778.58,4828.32 cw(c7787.97,4837.71) v1@7774.69,4837.71 ; v1(7769.19,4837.71) 7948.52,4658.37 7948.52,4622.7 v2(7968.11,4603.11) ; v2@7957.11,4603.11 ccw(c7930.55,4603.11) 7949.33,4621.89 ccw(c7968.11,4640.67) v2@7968.11,4614.11 ; v2@7961.11,4603.11 ccw(c7944.21,4603.11) 7956.16,4615.06 ccw(c7968.11,4627.01) v2@7968.11,4610.11
  MidLayer2 w4: v1(6906.86,4815.04) 6922.4,4799.5 7114.8,4799.5 7174.51,4859.21 7250.78,4859.21 7257.94,4866.37 7486.5,4866.37 7505.69,4847.19 7532.38,4847.19 7576.9,4891.71 7715.19,4891.71 v1(7769.19,4837.71) ; v1@7759.69,4837.71 ccw(c7736.76,4837.71) 7752.97,4853.93 ccw(c7769.19,4870.14) v1@7769.19,4847.21 ; v1@7763.69,4837.71 ccw(c7750.41,4837.71) 7759.8,4847.1 ccw(c7769.19,4856.49) v1@7769.19,4843.21
  Bottom Layer w4: v1(6247.52,3383.37) 6297.52,3433.37 6657.52,3433.37 6665.85,3425.04 6682.52,3425.04 6732.52,3375.04 v1(6906.86,3375.04) ; v1@6247.52,3388.87 ccw(c6247.52,3402.15) 6256.91,3392.76 ccw(c6266.3,3383.37) v1@6253.02,3383.37 ; v1@6247.52,3392.87 ccw(c6247.52,3415.81) 6263.74,3399.59 ccw(c6279.96,3383.37) v1@6257.02,3383.37 ; v1@6900.14,3368.32 ccw(c6883.92,3352.11) 6883.92,3375.04 ccw(c6883.92,3397.98) v1@6900.14,3381.76 ; v1@6902.97,3371.15 ccw(c6893.58,3361.76) 6893.58,3375.04 ccw(c6893.58,3388.32) v1@6902.97,3378.93
DB_MEM.BUS_A6: U7.D3 U8.C18 U12.29 U13.29 U16.5 U17.5 U61.91 | length 9078.4
  Top Layer w4: U8.C18@5567.17,4610.73 ccw(c5567.17,4628.45) 5579.7,4615.92 ; U8.C18@5574.51,4603.39 cw(c5592.23,4603.39) 5579.7,4615.92 ; v1@5641.02,4894.04 cw(c5618.09,4894.04) 5634.31,4877.82 cw(c5650.52,4861.61) v1@5650.52,4884.54 ; v1@5645.02,4894.04 cw(c5631.75,4894.04) 5641.13,4884.65 cw(c5650.52,4875.26) v1@5650.52,4888.54 ; v1(5650.52,4894.04) 5631.86,4875.37 5631.86,4825.54 5591.03,4784.71 5591.03,4724.74 5591.03,4720 5591.03,4710 5591.03,4643.27 cw(c5552.35,4643.27) 5579.7,4615.92 ; v1@5775.97,2803.52 ccw(c5750.47,2829.02) U61.91@5786.54,2829.02 ; v1@5778.8,2800.69 ccw(c5760.13,2819.36) U61.91@5786.54,2819.36 ; v1@5781.63,2797.86 ccw(c5769.79,2809.7) 5786.54,2809.7 ; v1(5782.69,2796.8) 5782.69,2800.54 5786.54,2804.39 U61.91@5786.53,2837.34 ; U61.91@5783.71,2821.32 cw(c5776.88,2814.49) 5786.54,2814.49 cw(c5796.19,2814.49) U61.91@5789.36,2821.32 ; 5786.54,2810.45 ccw(c5796.34,2810.45) v1@5789.41,2803.52 ; U17.5@6170.59,4844.72 6262.18,4844.72 6273.52,4833.37 v1(6281.86,4833.37) ; U17.5@6193.81,4839.07 cw(c6207.46,4825.41) 6207.46,4844.72 cw(c6207.46,4864.04) U17.5@6193.81,4850.38 ; 6266.34,4840.56 ccw(c6270.98,4845.2) v1@6275.43,4840.37 ; 6269.29,4837.61 ccw(c6273.81,4842.13) v1@6278.13,4837.42 ; U13.29@6619.41,3387.05 6654.53,3387.05 ; U13.29@6643,3381.8 cw(c6654.53,3371.77) 6654.53,3387.05 ; U13.29@6643.01,3392.3 ccw(c6654.53,3402.32) 6654.53,3387.05 ; v1(6665.19,3397.71) 6654.53,3387.05 ; v1(6795.52,4855.37) 6806.18,4844.72 U16.5@6845.59,4844.72 ; U16.5@6822.37,4839.07 ccw(c6808.72,4825.41) 6808.72,4844.72 ccw(c6808.72,4864.04) U16.5@6822.37,4850.38 ; v1(7181.86,3300.04) 7215.19,3300.04 ; v1@7185.75,3296.15 cw(c7195.14,3286.76) 7195.14,3300.04 cw(c7195.14,3313.32) v1@7185.75,3303.93 ; v1@7188.57,3293.32 cw(c7204.79,3277.11) 7204.79,3300.04 cw(c7204.79,3322.98) v1@7188.57,3306.76 ; v1@7208.47,3273.43 ccw(c7192.26,3289.64) 7215.19,3289.64 ccw(c7238.13,3289.64) v1@7221.91,3273.43 ; v1@7211.3,3270.6 ccw(c7201.91,3279.99) 7215.19,3279.99 ccw(c7228.47,3279.99) v1@7219.08,3270.6 ; v1(7215.19,3266.71) 7215.19,3300.04 ; 7255.71,3377.9 cw(c7270.29,3363.33) U12.29@7275.78,3383.19 ; 7258.86,3381.05 cw(c7265.2,3374.71) U12.29@7271.36,3381.23 ; 7260.57,3382.76 cw(c7272.39,3370.93) 7276.85,3387.05 ccw(c7270.86,3380.7) 7264.68,3386.87 ; 7261.77,3383.96 cw(c7268.03,3377.7) U12.29@7274.1,3384.14 ; 7265.42,3387.61 cw(c7274.49,3378.53) U12.29@7277.92,3390.9 ; U12.29@7269.46,3383.97 ccw(c7264.86,3382.06) 7264.86,3387.05 ; U12.29@7269.46,3390.12 cw(c7264.86,3392.04) 7264.86,3387.05 ; U12.29@7317.63,3381.39 cw(c7331.28,3367.73) 7331.28,3387.05 cw(c7331.28,3406.36) U12.29@7317.63,3392.7 ; v1@7350.14,3502.66 cw(c7333.92,3486.44) 7356.86,3486.44 cw(c7379.79,3486.44) v1@7363.57,3502.66 ; v1@7352.97,3505.49 cw(c7343.58,3496.1) 7356.86,3496.1 cw(c7370.14,3496.1) v1@7360.75,3505.49 ; v1(7356.86,3509.37) 7356.86,3395.37 7348.53,3387.05 U12.29@7294.41,3387.05 7264.86,3387.05 ; 7215.19,3300.04 7248.52,3300.04 7256.86,3308.37 7256.86,3379.05 7264.86,3387.05
  Top Layer w8: U7.D3@7869.69,4544.06 v2(7889.37,4563.74) ; U7.D3@7869.69,4550.06 ccw(c7869.69,4564.54) 7879.93,4554.3 ccw(c7890.17,4544.06) U7.D3@7875.69,4544.06 ; v2@7880.37,4563.74 cw(c7858.64,4563.74) 7874.01,4548.38 cw(c7889.37,4533.01) v2@7889.37,4554.74
  MidLayer1 w4: v1@6281.86,4823.87 cw(c6281.86,4800.94) 6298.07,4817.16 cw(c6314.29,4833.37) v1@6291.36,4833.37 ; v1@6281.86,4827.87 cw(c6281.86,4814.6) 6291.25,4823.99 cw(c6300.64,4833.37) v1@6287.36,4833.37 ; v1(6281.86,4833.37) 6304.86,4810.37 6601.52,4810.37 6628.52,4783.37 6722.52,4783.37 6746.52,4807.37 6815.19,4807.37 6823.52,4815.71 6823.52,4827.37 v1(6795.52,4855.37) ; v1@6795.52,4845.87 cw(c6795.52,4822.94) 6811.74,4839.16 cw(c6827.96,4855.37) v1@6805.02,4855.37 ; v1@6795.52,4849.87 cw(c6795.52,4836.6) 6804.91,4845.99 cw(c6814.3,4855.37) v1@6801.02,4855.37 ; v1@7741.81,3998.43 ccw(c7725.59,4014.64) 7748.52,4014.64 ccw(c7771.46,4014.64) v1@7755.24,3998.43 ; v1@7744.64,3995.6 ccw(c7735.25,4004.99) 7748.52,4004.99 ccw(c7761.8,4004.99) v1@7752.41,3995.6 ; v1(7748.52,3991.71) 7748.52,4266.71 7790.86,4309.04 7790.86,4375.04 7802.52,4386.71 7823.52,4386.71 7831.86,4395.04 7831.86,4535.71 7823.52,4544.04 7793.52,4544.04 7791.52,4546.04 7791.52,4620.37 7793.52,4622.37 7830.74,4622.37 v2(7889.37,4563.74) ; v2@7878.37,4563.74 ccw(c7851.82,4563.74) 7870.59,4582.52 ccw(c7889.37,4601.3) v2@7889.37,4574.74 ; v2@7882.37,4563.74 ccw(c7865.47,4563.74) 7877.42,4575.69 ccw(c7889.37,4587.64) v2@7889.37,4570.74
  MidLayer2 w4: v1@5643.81,4887.32 ccw(c5627.59,4871.11) 5627.59,4894.04 ccw(c5627.59,4916.98) v1@5643.81,4900.76 ; v1@5646.64,4890.15 ccw(c5637.25,4880.76) 5637.25,4894.04 ccw(c5637.25,4907.32) v1@5646.64,4897.93 ; v1(5650.52,4894.04) 5625.96,4894.04 5615.19,4904.81 5615.19,4950.04 5648.52,4983.37 5657.35,4992.2 5953.34,4992.2 5962.17,4983.37 6020.5,4925.04 6103.88,4925.04 6111.38,4917.54 6197.69,4917.54 6208.97,4906.26 v1(6281.86,4833.37) ; v1@6272.36,4833.37 ccw(c6249.42,4833.37) 6265.64,4849.59 ccw(c6281.86,4865.81) v1@6281.86,4842.87 ; v1@6276.36,4833.37 ccw(c6263.08,4833.37) 6272.47,4842.76 ccw(c6281.86,4852.15) v1@6281.86,4838.87 ; v1@6795.52,4845.87 cw(c6795.52,4822.94) 6811.74,4839.16 cw(c6827.96,4855.37) v1@6805.02,4855.37 ; v1@6795.52,4849.87 cw(c6795.52,4836.6) 6804.91,4845.99 cw(c6814.3,4855.37) v1@6801.02,4855.37 ; v1(6795.52,4855.37) 6859.19,4791.71 6859.4,4791.5 7118.12,4791.5 7177.82,4851.21 7254.09,4851.21 7261.26,4858.37 7483.19,4858.37 7649.85,4691.71 7823.52,4691.71 7854.96,4660.27 7854.96,4598.15 v2(7889.37,4563.74) ; v2@7878.37,4563.74 ccw(c7851.82,4563.74) 7870.59,4582.52 ccw(c7889.37,4601.3) v2@7889.37,4574.74 ; v2@7882.37,4563.74 ccw(c7865.47,4563.74) 7877.42,4575.69 ccw(c7889.37,4587.64) v2@7889.37,4570.74
  Bottom Layer w4: v1(5782.69,2796.8) 5800.89,2815 5953.29,2815 5982.33,2844.04 6312.19,2844.04 6326.52,2858.37 6420,2858.37 6428.37,2850 6604.53,2850 6630.49,2824.04 6824.9,2824.04 7150.9,3150.04 7206.86,3150.04 7215.19,3158.37 v1(7215.19,3266.71) ; v1@5782.69,2802.3 ccw(c5782.69,2815.58) 5792.08,2806.19 ccw(c5801.47,2796.8) v1@5788.19,2796.8 ; v1@5782.69,2806.3 ccw(c5782.69,2829.24) 5798.91,2813.02 ccw(c5815.13,2796.8) v1@5792.19,2796.8 ; v1@6658.47,3390.99 cw(c6642.26,3374.77) 6665.19,3374.77 cw(c6688.13,3374.77) v1@6671.91,3390.99 ; v1@6661.3,3393.82 cw(c6651.91,3384.43) 6665.19,3384.43 cw(c6678.47,3384.43) v1@6669.08,3393.82 ; v1(6665.19,3397.71) 6665.19,3366.71 6695.52,3336.37 6823.52,3336.37 6837.19,3350.04 7131.86,3350.04 v1(7181.86,3300.04) ; v1@7172.36,3300.04 ccw(c7149.42,3300.04) 7165.64,3316.26 ccw(c7181.86,3332.48) v1@7181.86,3309.54 ; v1@7176.36,3300.04 ccw(c7163.08,3300.04) 7172.47,3309.43 ccw(c7181.86,3318.82) v1@7181.86,3305.54 ; v1@7208.47,3259.99 cw(c7192.26,3243.77) 7215.19,3243.77 cw(c7238.13,3243.77) v1@7221.91,3259.99 ; v1@7211.3,3262.82 cw(c7201.91,3253.43) 7215.19,3253.43 cw(c7228.47,3253.43) v1@7219.08,3262.82 ; v1(7356.86,3509.37) 7448.52,3601.04 7448.52,3750.04 7581.86,3883.37 7581.86,3941.71 7631.86,3991.71 v1(7748.52,3991.71) ; v1@7356.86,3514.87 ccw(c7356.86,3528.15) 7366.25,3518.76 ccw(c7375.64,3509.37) v1@7362.36,3509.37 ; v1@7356.86,3518.87 ccw(c7356.86,3541.81) 7373.07,3525.59 ccw(c7389.29,3509.37) v1@7366.36,3509.37 ; v1@7741.81,3984.99 ccw(c7725.59,3968.77) 7725.59,3991.71 ccw(c7725.59,4014.64) v1@7741.81,3998.43 ; v1@7744.64,3987.82 ccw(c7735.25,3978.43) 7735.25,3991.71 ccw(c7735.25,4004.99) v1@7744.64,3995.6
DB_MEM.BUS_A7: U7.C3 U8.J21 U12.30 U13.30 U16.18 U17.18 U61.92 | length 10237.7
  Top Layer w4: U8.J21@5685.28,4367.17 v3(5704.96,4386.85) ; U8.J21@5685.28,4374.51 ccw(c5685.28,4392.23) 5697.81,4379.7 ccw(c5710.34,4367.17) U8.J21@5692.62,4367.17 ; U8.J21@5685.28,4374.67 ccw(c5685.28,4392.77) 5698.08,4379.97 ccw(c5710.88,4367.17) U8.J21@5692.78,4367.17 ; U61.92@5764.02,2853.36 ccw(c5757.19,2860.19) 5766.85,2860.19 ccw(c5776.51,2860.19) U61.92@5769.68,2853.36 ; U61.92@5766.85,2837.34 5766.85,2871.05 5789.28,2893.49 5803.64,2893.49 v1(5818.52,2908.37) ; U17.18@6170.59,4435.28 6247.62,4435.28 6257.86,4425.04 ; U17.18@6193.81,4429.62 cw(c6207.46,4415.96) 6207.46,4435.28 cw(c6207.46,4454.59) U17.18@6193.81,4440.93 ; v1@6266.35,4420.2 ccw(c6257.86,4415.17) 6257.86,4425.04 ; v1@6266.35,4429.88 cw(c6257.86,4434.91) 6257.86,4425.04 ; v1(6274.52,4425.04) 6257.86,4425.04 ; U13.30@6619.41,3418.54 6673.02,3418.54 6676.85,3422.37 ; U13.30@6642.63,3412.89 cw(c6656.28,3399.23) 6656.28,3418.54 cw(c6656.28,3437.86) U13.30@6642.63,3424.2 ; v1(6642.86,3291.71) 6701.19,3350.04 6701.19,3398.04 6676.85,3422.37 ; v1@6642.86,3297.21 ccw(c6642.86,3310.49) 6652.25,3301.1 ccw(c6661.64,3291.71) v1@6648.36,3291.71 ; v1@6642.86,3301.21 ccw(c6642.86,3324.14) 6659.07,3307.93 ccw(c6675.29,3291.71) v1@6652.36,3291.71 ; v1@6691.81,3475.32 cw(c6675.59,3459.11) 6698.52,3459.11 cw(c6721.46,3459.11) v1@6705.24,3475.32 ; v1@6694.64,3478.15 cw(c6685.25,3468.76) 6698.52,3468.76 cw(c6711.8,3468.76) v1@6702.41,3478.15 ; v1(6698.52,3482.04) 6698.52,3444.04 6676.85,3422.37 ; v1(6801.52,4437.37) 6848.52,4437.37 6848.52,4435.28 U16.18@6845.59,4435.28 ; v1@6803.65,4437.37 cw(c6803.65,4410.89) U16.18@6822.37,4429.62 ; v1@6805.41,4433.49 cw(c6814.8,4424.1) 6814.8,4437.37 cw(c6814.8,4450.65) v1@6805.41,4441.26 ; v1@6808.24,4430.66 cw(c6824.46,4414.44) 6824.46,4437.37 cw(c6824.46,4460.31) v1@6808.24,4444.09 ; 6813.31,4437.37 cw(c6813.31,4420.55) U16.18@6825.2,4432.45 ; 6813.79,4437.37 ccw(c6813.79,4449.52) U16.18@6822.37,4440.93 ; v1(7210.86,3428.04) 7240.5,3428.04 7250,3418.54 U12.30@7294.41,3418.54 ; v1@7214.75,3424.15 cw(c7224.14,3414.76) 7224.14,3428.04 cw(c7224.14,3441.32) v1@7214.75,3431.93 ; v1@7217.57,3421.32 cw(c7233.79,3405.11) 7233.79,3428.04 cw(c7233.79,3450.98) v1@7217.57,3434.76 ; U12.30@7271.19,3412.89 ccw(c7257.54,3399.23) 7257.54,3418.54 ccw(c7257.54,3437.86) U12.30@7271.19,3424.2 ; 5692.16,4374.05 cw(c5704.96,4361.24) 5704.96,4379.35 ccw(c5704.96,4361.24) 5692.16,4374.05 ; 5692.16,4374.05 ccw(c5679.35,4386.85) 5697.46,4386.85 cw(c5679.35,4386.85) 5692.16,4374.05
  Top Layer w8: U7.C3@7909.06,4544.06 v2(7928.74,4563.74) ; U7.C3@7909.06,4550.06 ccw(c7909.06,4564.54) 7919.3,4554.3 ccw(c7929.54,4544.06) U7.C3@7915.06,4544.06 ; v2@7919.74,4563.74 cw(c7898.01,4563.74) 7913.38,4548.38 cw(c7928.74,4533.01) v2@7928.74,4554.74
  MidLayer1 w4: v3@5705.61,4394.32 ccw(c5707.19,4412.36) 5718.83,4398.49 ; v3@5712.43,4386.2 cw(c5730.47,4384.62) 5718.83,4398.49 ; 5781.77,4410.71 5767.84,4410.71 ; v1(5956.86,4423.37) 5944.2,4410.71 5920,4410.71 5910,4410.71 5861.38,4410.71 5841.96,4410.71 5767.84,4410.71 ; v1(6274.52,4425.04) 6291.19,4441.71 6307.86,4441.71 6324.52,4425.04 6525.49,4425.04 6551.32,4399.21 6681.44,4399.21 6719.61,4437.37 v1(6801.52,4437.37) 6857.67,4437.37 6870,4425.04 6904.19,4425.04 6931.86,4452.71 6931.86,4483.37 6981.86,4533.37 7025.19,4533.37 7158.52,4666.71 7158.52,4708.37 7141.86,4725.04 6989.86,4725.04 6973.52,4741.37 6973.52,4766.37 6990.52,4783.37 7133.52,4783.37 7181.86,4735.04 7181.86,4640.71 7098.52,4557.37 7098.52,4425.37 7131.86,4392.04 7131.86,4317.36 7125,4310.5 7123.52,4309.02 7123.52,4196.37 7057.52,4130.37 7057.52,3959.04 6973.52,3875.04 6973.52,3825.04 6965.19,3816.71 6881.86,3816.71 6856.86,3791.71 6856.86,3691.71 6815.19,3650.04 6815.19,3616.71 6798.52,3600.04 6781.86,3600.04 6709.52,3672.37 6662.52,3672.37 6648.52,3658.37 6648.52,3523.71 6690.19,3482.04 v1(6698.52,3482.04) ; v1@6274.52,4430.54 ccw(c6274.52,4443.82) 6283.91,4434.43 ccw(c6293.3,4425.04) v1@6280.02,4425.04 ; v1@6274.52,4434.54 ccw(c6274.52,4457.48) 6290.74,4441.26 ccw(c6306.96,4425.04) v1@6284.02,4425.04 ; 6668.08,3504.15 ccw(c6698.52,3534.6) v1@6698.52,3491.54 ; 6674.91,3497.32 ccw(c6698.52,3520.94) v1@6698.52,3487.54 ; 6681.74,3490.49 ccw(c6698.52,3507.28) v1@6698.52,3483.54 ; v1@6794.81,4430.66 ccw(c6778.59,4414.44) 6778.59,4437.37 ccw(c6778.59,4460.31) v1@6794.81,4444.09 ; v1@6797.64,4433.49 ccw(c6788.25,4424.1) 6788.25,4437.37 ccw(c6788.25,4450.65) v1@6797.64,4441.26 ; v1@6805.41,4433.49 cw(c6814.8,4424.1) 6814.8,4437.37 cw(c6814.8,4450.65) v1@6805.41,4441.26 ; v1@6808.24,4430.66 cw(c6824.46,4414.44) 6824.46,4437.37 cw(c6824.46,4460.31) v1@6808.24,4444.09 ; 5718.83,4398.49 cw(c5748.34,4368.98) 5748.34,4410.71 5767.84,4410.71
  MidLayer2 w4: v1@5811.81,2901.66 cw(c5795.59,2885.44) 5818.52,2885.44 cw(c5841.46,2885.44) v1@5825.24,2901.66 ; v1@5814.64,2904.49 cw(c5805.25,2895.1) 5818.52,2895.1 cw(c5831.8,2895.1) v1@5822.41,2904.49 ; v1(5818.52,2908.37) 5818.52,2879.71 5856.86,2841.37 6309.88,2841.37 6351.88,2883.37 v1(6473.52,2883.37) ; v1(5956.86,4423.37) 5971.86,4408.37 6043.17,4408.37 6054.17,4397.37 6106.86,4397.37 6134.52,4425.04 v1(6274.52,4425.04) ; v1@6267.81,4418.32 ccw(c6251.59,4402.11) 6251.59,4425.04 ccw(c6251.59,4447.98) v1@6267.81,4431.76 ; v1@6270.64,4421.15 ccw(c6261.25,4411.76) 6261.25,4425.04 ccw(c6261.25,4438.32) v1@6270.64,4428.93 ; v1@6466.81,2876.66 ccw(c6450.59,2860.44) 6450.59,2883.37 ccw(c6450.59,2906.31) v1@6466.81,2890.09 ; v1@6469.64,2879.49 ccw(c6460.25,2870.1) 6460.25,2883.37 ccw(c6460.25,2896.65) v1@6469.64,2887.26 ; v1(7210.86,3428.04) 7252.63,3469.82 7281.52,3498.71 7281.52,3871.73 7418.5,4008.71 7713.71,4008.71 7877.42,4172.42 7947.94,4172.42 7970.52,4195 v1(7970.52,4261.37) ; v1@7210.86,3433.54 ccw(c7210.86,3446.82) 7220.25,3437.43 ccw(c7229.64,3428.04) v1@7216.36,3428.04 ; v1@7210.86,3437.54 ccw(c7210.86,3460.48) 7227.07,3444.26 ccw(c7243.29,3428.04) v1@7220.36,3428.04 ; v1@7963.81,4254.66 cw(c7947.59,4238.44) 7970.52,4238.44 cw(c7993.46,4238.44) v1@7977.24,4254.66 ; v1@7966.64,4257.49 cw(c7957.25,4248.1) 7970.52,4248.1 cw(c7983.8,4248.1) v1@7974.41,4257.49
  Bottom Layer w4: v1@6466.81,2890.09 ccw(c6450.59,2906.31) 6473.52,2906.31 ccw(c6496.46,2906.31) v1@6480.24,2890.09 ; v1@6469.64,2887.26 ccw(c6460.25,2896.65) 6473.52,2896.65 ccw(c6486.8,2896.65) v1@6477.41,2887.26 ; v1(6473.52,2883.37) 6473.52,2912.06 6528.17,2966.71 6748.52,2966.71 6773.52,2991.71 6923.52,2991.71 6942.19,3010.37 6942.19,3239.71 6916.19,3265.71 6807.86,3265.71 6781.86,3291.71 v1(6642.86,3291.71) ; v1@6646.75,3287.82 cw(c6656.14,3278.43) 6656.14,3291.71 cw(c6656.14,3304.99) v1@6646.75,3295.6 ; v1@6649.57,3284.99 cw(c6665.79,3268.77) 6665.79,3291.71 cw(c6665.79,3314.64) v1@6649.57,3298.43 ; v1@6698.52,3472.54 cw(c6698.52,3449.61) 6714.74,3465.82 cw(c6730.96,3482.04) v1@6708.02,3482.04 ; v1@6698.52,3476.54 cw(c6698.52,3463.26) 6707.91,3472.65 cw(c6717.3,3482.04) v1@6704.02,3482.04 ; v1(6698.52,3482.04) 6730.52,3450.04 6837.21,3450.04 6862.88,3424.37 7207.19,3424.37 v1(7210.86,3428.04) ; 7179.07,3424.37 ccw(c7179.07,3459.83) v1@7204.14,3434.76 ; 7188.73,3424.37 ccw(c7188.73,3450.17) v1@7206.97,3431.93 ; 7196.77,3424.37 cw(c7196.77,3413.96) v1@7204.14,3421.32 ; 7198.39,3424.37 ccw(c7198.39,3440.51) v1@7209.8,3429.1 ; v2(7928.74,4563.74) 7948.38,4583.37 7978.86,4583.37 7987.19,4575.04 7987.19,4494.71 8040.19,4441.71 8040.19,4331.04 v1(7970.52,4261.37) ; v2@7928.74,4570.74 ccw(c7928.74,4587.64) 7940.69,4575.69 ccw(c7952.64,4563.74) v2@7935.74,4563.74 ; v2@7928.74,4574.74 ccw(c7928.74,4601.3) 7947.52,4582.52 ccw(c7966.3,4563.74) v2@7939.74,4563.74 ; v1@7970.52,4266.87 ccw(c7970.52,4280.15) 7979.91,4270.76 ccw(c7989.3,4261.37) v1@7976.02,4261.37 ; v1@7970.52,4270.87 ccw(c7970.52,4293.81) 7986.74,4277.59 ccw(c8002.96,4261.37) v1@7980.02,4261.37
